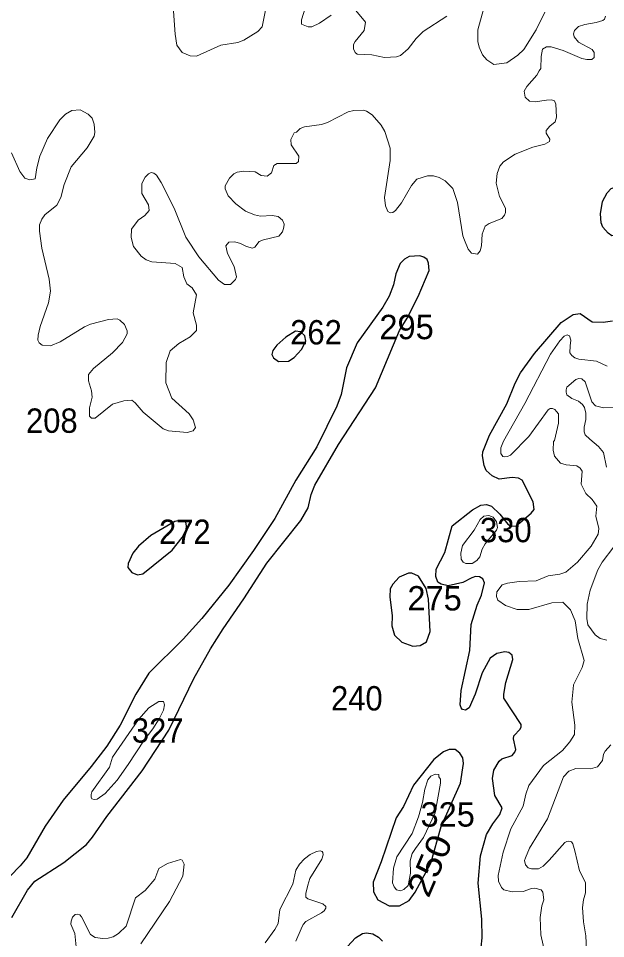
# Model space of a CAD drawing. Extents: x 499.9 to 555.3, y 9281.5 to 9336.8.
# Drawn here: x 545.72 to 549.58, y 9324.03 to 9330.07 of the extents above; entities that cross this region are included whole.
import ezdxf
from ezdxf.enums import TextEntityAlignment as Align

# ---------------------------------------------------------------- set-up
doc = ezdxf.new("R2010")
doc.units = 0
doc.header["$LTSCALE"] = 0.064
doc.layers.add('1', color=7, linetype='Continuous', lineweight=25)
doc.layers.add('2', color=7, linetype='Continuous', lineweight=13)
doc.layers.add('21', color=7, linetype='Continuous')
doc.layers.add('61', color=7, linetype='Continuous')

msp = doc.modelspace()

# ---------------------------------------------------------------- linework, layer by layer
at = {"layer": '1'}
for points in [[(549.5469, 9328.7898), (549.5606, 9328.8722), (549.5923, 9328.9278), (549.6176, 9328.9578), (549.6481, 9328.9689), (549.6872, 9328.9658), (549.7443, 9328.9395), (549.7806, 9328.8917), (549.7812, 9328.8385), (549.7646, 9328.777), (549.7229, 9328.7059), (549.6993, 9328.6716), (549.6718, 9328.652), (549.6227, 9328.6473), (549.5983, 9328.6636), (549.5625, 9328.7031), (549.5519, 9328.7322)], [(547.4974, 9327.8239), (547.5351, 9327.8475), (547.5837, 9327.8992), (547.6119, 9327.9553), (547.6057, 9327.9897), (547.5776, 9328.0158), (547.5432, 9328.0199), (547.4817, 9327.9803), (547.4213, 9327.9282), (547.3952, 9327.8928), (547.389, 9327.8678), (547.4004, 9327.8449), (547.4317, 9327.822)], [(546.7342, 9326.5831), (546.8006, 9326.6653), (546.8253, 9326.7146), (546.8275, 9326.7429), (546.8236, 9326.7649), (546.8079, 9326.7764), (546.7814, 9326.7772), (546.7524, 9326.7712), (546.593, 9326.6789), (546.5138, 9326.6075), (546.4752, 9326.5631), (546.4447, 9326.4943), (546.443, 9326.4672), (546.4689, 9326.436), (546.5056, 9326.4208), (546.5411, 9326.4276)], [(548.3155, 9325.951), (548.3635, 9325.9567), (548.4046, 9325.9796), (548.4288, 9326.0485), (548.4182, 9326.2611), (548.4018, 9326.3312), (548.3513, 9326.4117), (548.3087, 9326.431), (548.2872, 9326.4314), (548.2254, 9326.4057), (548.1839, 9326.3582), (548.1664, 9326.3272), (548.1648, 9326.2762), (548.179, 9326.1506), (548.1777, 9326.0861), (548.1934, 9326.0234), (548.2419, 9325.979)], [(548.3298, 9324.3352), (548.4322, 9324.5273), (548.5003, 9324.7669), (548.6278, 9325.0516), (548.6469, 9325.1813), (548.6438, 9325.2194), (548.6246, 9325.2488), (548.592, 9325.2726), (548.5539, 9325.2724), (548.5166, 9325.2583), (548.452, 9325.208), (548.3186, 9325.0398), (548.2527, 9324.8995), (548.2044, 9324.8247), (548.1074, 9324.536), (548.0553, 9324.403), (548.0568, 9324.3386), (548.0848, 9324.2853), (548.1601, 9324.2465), (548.2275, 9324.2455), (548.2904, 9324.2818)]]:
    msp.add_lwpolyline(points, close=True, dxfattribs=at)
for points in [[(548.069, 9327.6477), (548.2276, 9328.0255), (548.2772, 9328.1062), (548.3509, 9328.2474), (548.4224, 9328.4178), (548.4177, 9328.467), (548.4083, 9328.4917), (548.388, 9328.5065), (548.3605, 9328.516), (548.2906, 9328.5097), (548.261, 9328.4933), (548.2308, 9328.4643), (548.203, 9328.397), (548.187, 9328.3239), (548.1594, 9328.2499), (548.117, 9328.1775), (547.9488, 9327.9443), (547.8799, 9327.7785), (547.8435, 9327.6041), (547.8149, 9327.5288), (547.6845, 9327.2614), (547.5468, 9327.0426), (547.4087, 9326.7896), (547.2692, 9326.5802), (547.1058, 9326.3527), (546.9279, 9326.1329), (546.8055, 9325.9984), (546.5813, 9325.7741), (546.4963, 9325.6365), (546.3933, 9325.4336), (546.3047, 9325.2943), (546.2029, 9325.162), (546.0172, 9324.941), (545.9007, 9324.7704), (545.7794, 9324.5621), (545.7352, 9324.509), (545.5991, 9324.372)], [(548.7712, 9325.7773), (548.7248, 9325.6373), (548.6849, 9325.5478), (548.66, 9325.5316), (548.641, 9325.5349), (548.6318, 9325.5478), (548.6249, 9325.5657), (548.6324, 9325.6606), (548.6883, 9325.924), (548.6974, 9326.0937), (548.7379, 9326.22), (548.7666, 9326.287), (548.7847, 9326.3668), (548.7751, 9326.3938), (548.7533, 9326.4071), (548.7268, 9326.4087), (548.7028, 9326.3994), (548.643, 9326.3692), (548.5474, 9326.3473), (548.5009, 9326.3589), (548.4784, 9326.3719), (548.4661, 9326.4087), (548.469, 9326.4569), (548.5259, 9326.5668), (548.5737, 9326.7426), (548.7076, 9326.8468), (548.7617, 9326.8767), (548.7981, 9326.8828), (548.8307, 9326.8706), (548.8872, 9326.8181), (548.9391, 9326.7518), (548.9573, 9326.7416), (548.9923, 9326.7402), (549.0925, 9326.8246), (549.1111, 9326.8495), (549.1049, 9326.8986), (549.0332, 9327.0411), (549.0095, 9327.0542), (548.9685, 9327.06), (548.8816, 9327.0486), (548.8365, 9327.0713), (548.796, 9327.1062), (548.7837, 9327.1374), (548.7731, 9327.2012), (548.7755, 9327.2274), (548.8185, 9327.3363), (548.933, 9327.5432), (548.988, 9327.6784), (549.0223, 9327.7464), (549.1139, 9327.8725), (549.29, 9328.0769), (549.3673, 9328.1306), (549.414, 9328.1357), (549.4938, 9328.0823), (549.5648, 9328.0793), (549.6274, 9328.0884)], [(545.6808, 9324.1706), (545.7827, 9324.3488), (545.8323, 9324.409), (546.0226, 9324.5308), (546.1705, 9324.649), (546.2114, 9324.6976), (546.3039, 9324.8325), (546.5362, 9325.1321), (546.7119, 9325.3993), (546.8768, 9325.7384), (546.9866, 9325.9352), (547.0685, 9326.0651), (547.2055, 9326.2619), (547.3549, 9326.4963), (547.5795, 9326.7776), (547.6267, 9326.8596), (547.6467, 9326.9475), (547.6714, 9327.0092), (547.8269, 9327.2753), (548.069, 9327.6477)], [(548.763, 9323.9748), (548.7695, 9324.0361), (548.7679, 9324.1579), (548.7442, 9324.395), (548.7585, 9324.5741), (548.7998, 9324.7141), (548.8397, 9324.7841), (548.8867, 9324.8456), (548.9028, 9324.8908), (548.8536, 9324.9708), (548.8382, 9325.0826), (548.8478, 9325.1368), (548.8828, 9325.1962), (548.9002, 9325.2116), (548.9685, 9325.234), (548.986, 9325.2562), (548.9925, 9325.2724), (548.976, 9325.343), (548.9785, 9325.3634), (549.0195, 9325.4075), (549.0274, 9325.4222), (549.0269, 9325.4375), (548.9131, 9325.6103), (548.9137, 9325.6374), (548.9257, 9325.7127), (548.9714, 9325.8631), (548.9669, 9325.8917)], [(548.9669, 9325.8917), (548.9462, 9325.9096), (548.9199, 9325.9139), (548.8675, 9325.9031), (548.8233, 9325.8722), (548.7712, 9325.7773)], [(547.8861, 9323.9805), (547.9373, 9324.036), (547.9843, 9324.0658), (548.0105, 9324.0693), (548.0526, 9324.0635), (548.0888, 9324.0418), (548.115, 9324.0152)]]:
    msp.add_lwpolyline(points, dxfattribs=at)
at = {"layer": '2'}
for points in [[(549.182, 9330.1143), (549.1248, 9329.9988), (549.0448, 9329.8709), (549.0053, 9329.832), (548.9321, 9329.7828), (548.8469, 9329.771), (548.7999, 9329.8009), (548.7715, 9329.8353), (548.7503, 9329.8843), (548.7426, 9329.9225), (548.7426, 9329.9981), (548.8362, 9330.3412)], [(546.7988, 9329.851), (546.7654, 9329.8979), (546.753, 9329.9703), (546.7435, 9330.1215), (546.7328, 9330.1449), (546.7143, 9330.1637)], [(547.7789, 9330.0964), (547.7025, 9330.0424), (547.6523, 9330.0189), (547.6277, 9330.0192), (547.5843, 9330.0352), (547.584, 9330.065), (547.6181, 9330.1765)], [(547.3511, 9330.1492), (547.3254, 9330.0183), (547.2957, 9329.9878), (547.2057, 9329.9301), (547.1661, 9329.9153), (547.053, 9329.898), (546.8939, 9329.8265), (546.8524, 9329.8278), (546.7988, 9329.851)], [(548.5389, 9330.0895), (548.3836, 9329.9882), (548.3361, 9329.9421), (548.2851, 9329.8736), (548.2337, 9329.83), (548.2077, 9329.8215), (548.1289, 9329.8183), (548.0454, 9329.8358), (547.9485, 9329.8392), (547.9361, 9329.8498), (547.9241, 9329.8742), (547.9249, 9329.9033), (547.9354, 9329.9233), (547.9942, 9329.9951), (548.004, 9330.0493), (547.9185, 9330.1527)], [(549.4031, 9330.0215), (549.4445, 9330.035), (549.52, 9330.0462), (549.5623, 9330.0592), (549.5749, 9330.0694), (549.5795, 9330.0889)], [(549.4934, 9329.8691), (549.4032, 9329.9171), (549.3749, 9329.9538), (549.3712, 9329.9726), (549.376, 9329.9941), (549.4031, 9330.0215)], [(547.1605, 9329.0639), (547.2051, 9329.0718), (547.2797, 9329.0656), (547.319, 9329.042), (547.357, 9329.0387), (547.3866, 9329.0603), (547.4012, 9329.1082), (547.4241, 9329.1208), (547.5477, 9329.1218), (547.563, 9329.1348), (547.5659, 9329.1704), (547.5153, 9329.2437), (547.5141, 9329.2787), (547.5363, 9329.3229), (547.55, 9329.3276), (547.5746, 9329.3518), (547.6023, 9329.3628), (547.7144, 9329.3769), (547.754, 9329.3911), (547.8902, 9329.4604), (547.9284, 9329.4697), (547.9887, 9329.4711), (548.0104, 9329.4648), (548.0478, 9329.4415), (548.1068, 9329.374), (548.13, 9329.3321), (548.1656, 9329.2214), (548.1663, 9329.142), (548.1283, 9328.8976), (548.1349, 9328.8427), (548.1503, 9328.8052), (548.166, 9328.7983), (548.1841, 9328.7998), (548.2015, 9328.8127), (548.2399, 9328.8625), (548.3053, 9328.9769), (548.3416, 9329.0192), (548.4122, 9329.04), (548.4496, 9329.0399), (548.4885, 9329.0285), (548.5266, 9329.0077), (548.5773, 9328.956), (548.6074, 9328.8642), (548.6431, 9328.6465), (548.6551, 9328.6177), (548.679, 9328.5594), (548.7007, 9328.5331), (548.7391, 9328.5264), (548.7576, 9328.5481), (548.7662, 9328.5816), (548.7693, 9328.6563), (548.7896, 9328.7094), (548.8173, 9328.7279), (548.8989, 9328.761), (548.9162, 9328.7824), (548.9236, 9328.8002), (548.9235, 9328.8272), (548.8839, 9328.9039), (548.8621, 9328.9926), (548.8682, 9329.0551), (548.8863, 9329.1042), (548.911, 9329.133), (548.9877, 9329.1832), (549.1023, 9329.2278), (549.181, 9329.2484), (549.2129, 9329.265), (549.214, 9329.2816), (549.1906, 9329.3214), (549.1918, 9329.3384), (549.2142, 9329.3666), (549.25, 9329.3951), (549.259, 9329.4263), (549.2534, 9329.5103), (549.2458, 9329.5335), (549.2262, 9329.539), (549.1938, 9329.5365), (549.1181, 9329.5271), (549.0808, 9329.5303), (549.0532, 9329.5558), (549.0467, 9329.5962), (549.0645, 9329.6278), (549.1287, 9329.7014), (549.1455, 9329.7292), (549.1558, 9329.7461), (549.1581, 9329.8238), (549.1675, 9329.8717), (549.1938, 9329.8863), (549.2239, 9329.888), (549.302, 9329.8631), (549.4255, 9329.8116), (549.4577, 9329.8031), (549.4905, 9329.804), (549.5054, 9329.8173), (549.5068, 9329.8495), (549.4934, 9329.8691)], [(545.6787, 9329.1912), (545.7325, 9329.0693), (545.7669, 9329.0239), (545.7984, 9329.0131), (545.8331, 9329.0203), (545.8444, 9329.0917), (545.8657, 9329.169), (545.916, 9329.2851), (545.9952, 9329.4089), (546.0327, 9329.4446), (546.075, 9329.4684), (546.129, 9329.4743), (546.1813, 9329.4462), (546.2089, 9329.4182), (546.2226, 9329.379), (546.2263, 9329.325), (546.221, 9329.3004), (546.1764, 9329.224), (546.0715, 9329.0996), (546.0252, 9328.9827), (546.002, 9328.8976), (545.9764, 9328.8481), (545.8984, 9328.7837), (545.8769, 9328.7558), (545.862, 9328.7185), (545.8621, 9328.6772), (545.8779, 9328.565), (545.927, 9328.362), (545.9349, 9328.2825), (545.9219, 9328.2053), (545.8661, 9328.0515), (545.8538, 9327.9938), (545.8508, 9327.9607)], [(546.1585, 9328.0488), (546.1977, 9328.0664), (546.3146, 9328.0979), (546.3716, 9328.1007), (546.3908, 9328.0924), (546.4217, 9328.0642), (546.4376, 9328.0222), (546.4379, 9328.003), (546.4077, 9327.9451), (546.343, 9327.8771), (546.2167, 9327.7747), (546.1839, 9327.736), (546.1852, 9327.6942), (546.204, 9327.6292), (546.2088, 9327.5875), (546.1899, 9327.5161), (546.1903, 9327.4623), (546.2049, 9327.4497), (546.2276, 9327.448), (546.3425, 9327.5406), (546.4171, 9327.5627), (546.47, 9327.5662), (546.4915, 9327.5492), (546.543, 9327.4883), (546.6743, 9327.3784), (546.7088, 9327.3655), (546.8318, 9327.3546), (546.8712, 9327.3651), (546.8866, 9327.387), (546.8711, 9327.4382), (546.8453, 9327.477), (546.7326, 9327.5806), (546.6915, 9327.6812), (546.6944, 9327.8152), (546.7214, 9327.8908), (546.778, 9327.9398), (546.8517, 9327.9833), (546.8927, 9328.0247), (546.8929, 9328.0604), (546.8726, 9328.141), (546.8939, 9328.2586), (546.8661, 9328.3058), (546.8311, 9328.3318), (546.8115, 9328.3764), (546.7988, 9328.4384), (546.753, 9328.4637), (546.601, 9328.4751), (546.5621, 9328.4879), (546.5306, 9328.513), (546.4803, 9328.577), (546.4636, 9328.635), (546.4661, 9328.6907), (546.5096, 9328.7502), (546.5541, 9328.7807), (546.5839, 9328.8136), (546.579, 9328.8497), (546.5355, 9328.9248), (546.5345, 9328.9908), (546.5569, 9329.0318), (546.5781, 9329.0525), (546.5951, 9329.0616), (546.6131, 9329.057), (546.6307, 9329.0448), (546.6613, 9328.9971), (546.7463, 9328.8274), (546.8243, 9328.6365), (546.9085, 9328.5091), (547.038, 9328.3557), (547.0778, 9328.3263), (547.1172, 9328.3257), (547.1495, 9328.3595), (547.1571, 9328.378), (547.141, 9328.4455), (547.0964, 9328.5293), (547.0873, 9328.5804), (547.1072, 9328.6039), (547.1453, 9328.6068), (547.1821, 9328.5961), (547.2218, 9328.5752), (547.2618, 9328.5661), (547.278, 9328.5709), (547.3065, 9328.6086), (547.3334, 9328.6203), (547.4341, 9328.644), (547.4579, 9328.6728), (547.4666, 9328.7032), (547.4693, 9328.7237), (547.4581, 9328.7502), (547.4309, 9328.774), (547.3905, 9328.7789), (547.3141, 9328.7759), (547.2752, 9328.7838), (547.2147, 9328.8078), (547.152, 9328.8559), (547.1018, 9328.9095)], [(547.1018, 9328.9095), (547.0814, 9328.9543), (547.083, 9328.975), (547.1101, 9329.0246), (547.1383, 9329.0526), (547.1605, 9329.0639)], [(545.8508, 9327.9607), (545.861, 9327.9429), (545.8794, 9327.9279), (545.9344, 9327.9235), (545.9987, 9327.9509), (546.1585, 9328.0488)], [(549.2804, 9326.4237), (549.3192, 9326.4383), (549.3962, 9326.5025), (549.4868, 9326.6074), (549.5315, 9326.687), (549.5364, 9326.7252), (549.5163, 9326.8046), (549.5239, 9326.8701), (549.4937, 9326.9152), (549.4523, 9326.9553), (549.4209, 9327.0151), (549.4276, 9327.1011), (549.4133, 9327.1216), (549.3917, 9327.1363), (549.3211, 9327.1431), (549.2844, 9327.1539), (549.2456, 9327.1987), (549.2367, 9327.2393), (549.239, 9327.2955), (549.2455, 9327.3029), (549.2709, 9327.4167), (549.2708, 9327.4764), (549.2596, 9327.493), (549.2477, 9327.506), (549.2327, 9327.5132), (549.2173, 9327.5125), (549.2031, 9327.5045), (549.0771, 9327.3276), (548.9556, 9327.2067), (548.9378, 9327.1975), (548.9188, 9327.1943), (548.9071, 9327.1982), (548.8927, 9327.2172), (548.8932, 9327.2533), (548.9114, 9327.2986), (549.05, 9327.5446), (549.2185, 9327.8698), (549.28, 9327.9571), (549.3099, 9327.9882), (549.3282, 9327.9955), (549.3445, 9327.9899), (549.3534, 9327.9608), (549.3479, 9327.9247), (549.3473, 9327.8774), (549.3587, 9327.8613), (549.3782, 9327.8461), (549.4056, 9327.8364), (549.5217, 9327.824), (549.5917, 9327.791)], [(549.3594, 9327.5778), (549.3266, 9327.6011), (549.3223, 9327.6194), (549.3212, 9327.6349), (549.3255, 9327.6526), (549.386, 9327.7039), (549.4044, 9327.7088), (549.4242, 9327.7072), (549.446, 9327.688), (549.4917, 9327.5554), (549.5153, 9327.5296), (549.5682, 9327.5174), (549.6465, 9327.5186)], [(549.4523, 9327.4405), (549.4523, 9327.4827), (549.4428, 9327.5198), (549.4293, 9327.5395), (549.4024, 9327.5596), (549.3594, 9327.5778)], [(549.5875, 9327.1277), (549.5679, 9327.223), (549.535, 9327.2638), (549.4779, 9327.3116), (549.4472, 9327.3392), (549.4401, 9327.3595), (549.4411, 9327.3909), (549.4523, 9327.4405)], [(549.5892, 9325.9908), (549.5447, 9326.0019), (549.5119, 9326.0251), (549.4652, 9326.0925), (549.4588, 9326.1338), (549.4603, 9326.2286), (549.4797, 9326.3192), (549.5312, 9326.4535), (549.5579, 9326.5037), (549.6348, 9326.6034)], [(548.9019, 9326.3548), (548.936, 9326.366), (549.013, 9326.3773), (549.1259, 9326.3803), (549.2041, 9326.4138), (549.2804, 9326.4237)], [(549.1816, 9323.9398), (549.1564, 9324.0552), (549.1517, 9324.1691), (549.1627, 9324.2462), (549.1753, 9324.2852), (549.1694, 9324.3372), (549.1574, 9324.3512), (549.1174, 9324.3623), (549.0934, 9324.3608), (549.04, 9324.3399), (548.9685, 9324.3382), (548.9134, 9324.3527), (548.8964, 9324.3662), (548.8781, 9324.4079), (548.8762, 9324.4461), (548.9079, 9324.5988), (548.9587, 9324.7516), (549.04, 9324.902), (549.0563, 9324.9791), (549.0778, 9325.0372), (549.1723, 9325.1677), (549.2979, 9325.2665), (549.3472, 9325.3238), (549.3758, 9325.3716), (549.3791, 9325.4335), (549.3601, 9325.5831), (549.3677, 9325.6724), (549.3699, 9325.6984), (549.4265, 9325.8116), (549.4397, 9325.8566), (549.3984, 9326.0026), (549.3813, 9326.1178), (549.3508, 9326.1904), (549.2994, 9326.2401), (549.2288, 9326.2371), (549.0775, 9326.1929), (549.0004, 9326.1929), (548.924, 9326.2198), (548.8737, 9326.2528), (548.8636, 9326.2778), (548.8666, 9326.3081), (548.9019, 9326.3548)], [(549.4587, 9323.9152), (549.4507, 9324.0489), (549.4365, 9324.1405), (549.4301, 9324.236), (549.4351, 9324.2852), (549.4491, 9324.333), (549.4491, 9324.4007), (549.4091, 9324.4762), (549.3792, 9324.6083), (549.3651, 9324.6529), (549.3562, 9324.667), (549.3402, 9324.6709), (549.3257, 9324.6683), (549.3124, 9324.663), (549.2104, 9324.5471), (549.1709, 9324.5074), (549.141, 9324.4902), (549.0934, 9324.4898), (549.0721, 9324.4963), (549.0547, 9324.5168), (549.0485, 9324.5447), (549.0559, 9324.5627), (549.0812, 9324.6243), (549.2, 9324.8178), (549.305, 9325.0935), (549.3395, 9325.1309), (549.3852, 9325.1474), (549.481, 9325.1456), (549.5275, 9325.159), (549.5615, 9325.2006), (549.5669, 9325.2417), (549.5778, 9325.2631), (549.6149, 9325.3028)], [(547.5472, 9324.0138), (547.5804, 9324.0959), (547.5953, 9324.1229), (547.6129, 9324.1427), (547.7149, 9324.1999), (547.732, 9324.2138), (547.7428, 9324.2306), (547.7423, 9324.2419), (547.7233, 9324.2607), (547.6261, 9324.2915), (547.6128, 9324.3045), (547.6122, 9324.3281), (547.6251, 9324.3823), (547.6393, 9324.427), (547.7165, 9324.5534), (547.7262, 9324.5823), (547.7239, 9324.597), (547.7186, 9324.604), (547.7068, 9324.6086), (547.6818, 9324.6037), (547.6405, 9324.5831), (547.6036, 9324.5555), (547.5711, 9324.5199), (547.5462, 9324.4808), (547.5262, 9324.3888), (547.441, 9324.2214), (547.4301, 9324.13), (547.4092, 9324.0909), (547.3457, 9324.0033)], [(546.5275, 9323.997), (546.716, 9324.2758), (546.8038, 9324.4405), (546.8134, 9324.5198), (546.7995, 9324.5463), (546.7893, 9324.5513), (546.7029, 9324.525), (546.6471, 9324.4916), (546.6208, 9324.4214), (546.5563, 9324.3471), (546.4938, 9324.2986), (546.4309, 9324.1136), (546.3812, 9324.0654), (546.3471, 9324.0427), (546.3145, 9324.0332), (546.2779, 9324.0315), (546.2283, 9324.0394), (546.1978, 9324.0586), (546.1378, 9324.1739), (546.1283, 9324.187), (546.1119, 9324.1929), (546.0961, 9324.1893), (546.0784, 9324.1727), (546.0694, 9324.146), (546.0687, 9324.1252), (546.0942, 9324.0641), (546.1037, 9323.9769)]]:
    msp.add_lwpolyline(points, dxfattribs=at)
for points in [[(548.756, 9326.5384), (548.7712, 9326.5886), (548.7911, 9326.6231), (548.8655, 9326.7134), (548.8713, 9326.7315), (548.864, 9326.7674), (548.8434, 9326.7993), (548.8131, 9326.8098), (548.7823, 9326.8053), (548.7581, 9326.7829), (548.7188, 9326.7125), (548.6403, 9326.6135), (548.6294, 9326.5618), (548.6315, 9326.5232), (548.6452, 9326.5039), (548.663, 9326.4938), (548.7042, 9326.494), (548.7347, 9326.5138)], [(546.445, 9325.1745), (546.5494, 9325.3337), (546.6072, 9325.4098), (546.6476, 9325.4743), (546.6762, 9325.531), (546.6827, 9325.5675), (546.6772, 9325.5893), (546.6468, 9325.589), (546.5807, 9325.5476), (546.5123, 9325.4695), (546.3429, 9325.2238), (546.3214, 9325.1564), (546.2058, 9324.9942), (546.2009, 9324.9766), (546.2022, 9324.9609), (546.2066, 9324.9483), (546.2207, 9324.9441), (546.2404, 9324.9468), (546.2935, 9324.9837), (546.3737, 9325.0717)], [(548.3324, 9324.6232), (548.3839, 9324.6961), (548.4611, 9324.8582), (548.4974, 9325.0522), (548.4972, 9325.0785), (548.4866, 9325.0932), (548.4853, 9325.108), (548.4607, 9325.1117), (548.4337, 9325.0974), (548.4124, 9325.0741), (548.3929, 9325.0125), (548.3781, 9324.9255), (548.3526, 9324.8308), (548.3096, 9324.7216), (548.21, 9324.5675), (548.1881, 9324.4944), (548.1824, 9324.3976), (548.1922, 9324.3714), (548.208, 9324.3516), (548.233, 9324.3457), (548.2559, 9324.3542), (548.2849, 9324.3806), (548.3003, 9324.461), (548.2965, 9324.5425), (548.3111, 9324.5901)]]:
    msp.add_lwpolyline(points, close=True, dxfattribs=at)

# ---------------------------------------------------------------- texts
at = {"layer": '21'}
for s, p in [('295', (548.0954, 9327.9675)), ('275', (548.2793, 9326.1861)), ('325', (548.3655, 9324.7668))]:
    msp.add_text(s, height=0.16, dxfattribs=at).set_placement(p)
at = {"layer": '21', "width": 0.95}
for s, p in [('262', (547.5093, 9327.933)), ('208', (545.7739, 9327.3526)), ('272', (546.6474, 9326.6228)), ('330', (548.7562, 9326.6343)), ('240', (547.7775, 9325.5293)), ('327', (546.4692, 9325.3184))]:
    msp.add_text(s, height=0.16, dxfattribs=at).set_placement(p)
at = {"layer": '61', "width": 1.15}
msp.add_text('250', height=0.16, rotation=66.801, dxfattribs=at).set_placement((548.4991, 9324.4802), align=Align.CENTER)

doc.saveas('drawing.dxf')
